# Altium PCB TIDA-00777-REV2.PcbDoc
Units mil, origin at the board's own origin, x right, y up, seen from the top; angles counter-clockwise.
Board outline 1496.06 x 4202.76 mil, 4 copper layers (Top Layer, Layer 2, Layer 3, Bottom Layer), stack 70.356 mil thick; 108 components, 64 nets, 316 pads, 62 vias.
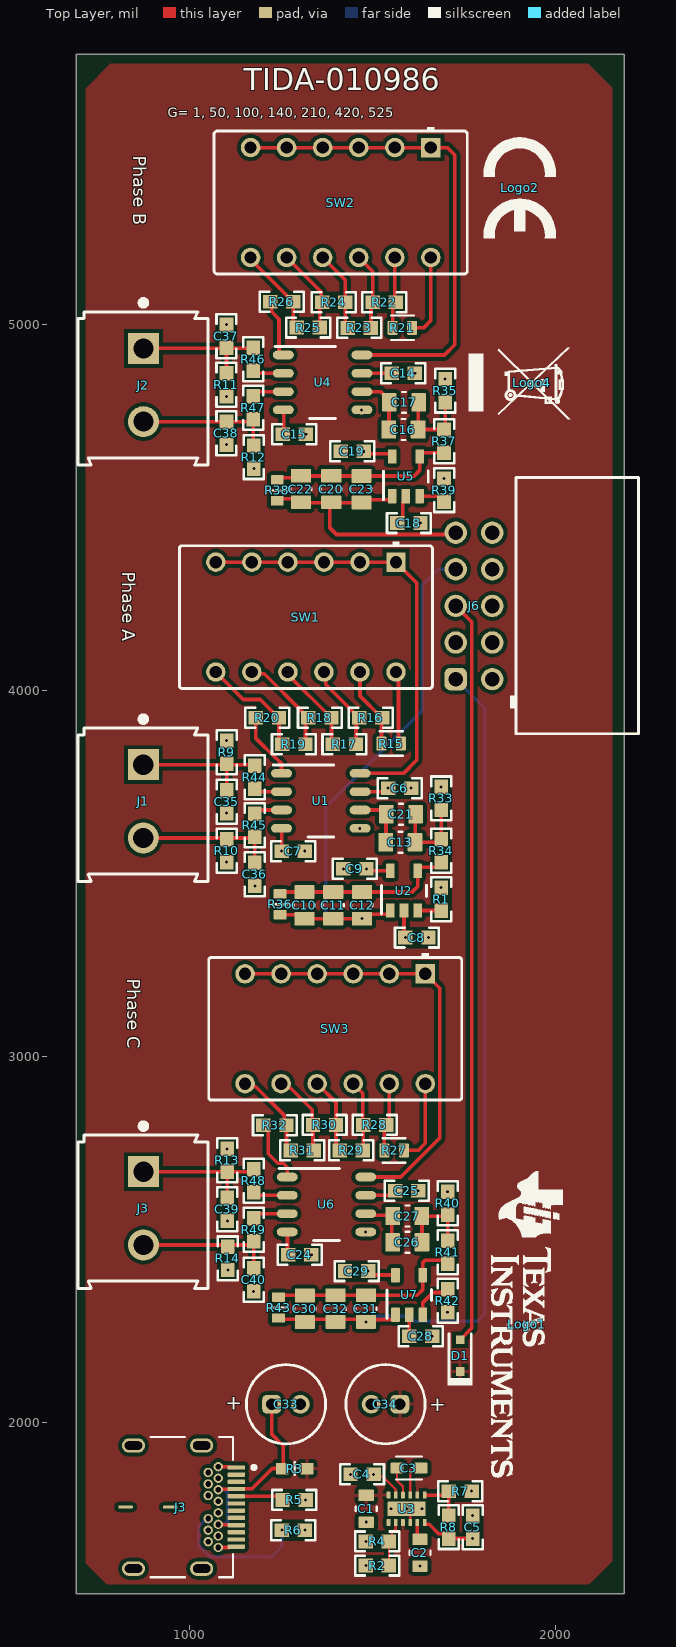
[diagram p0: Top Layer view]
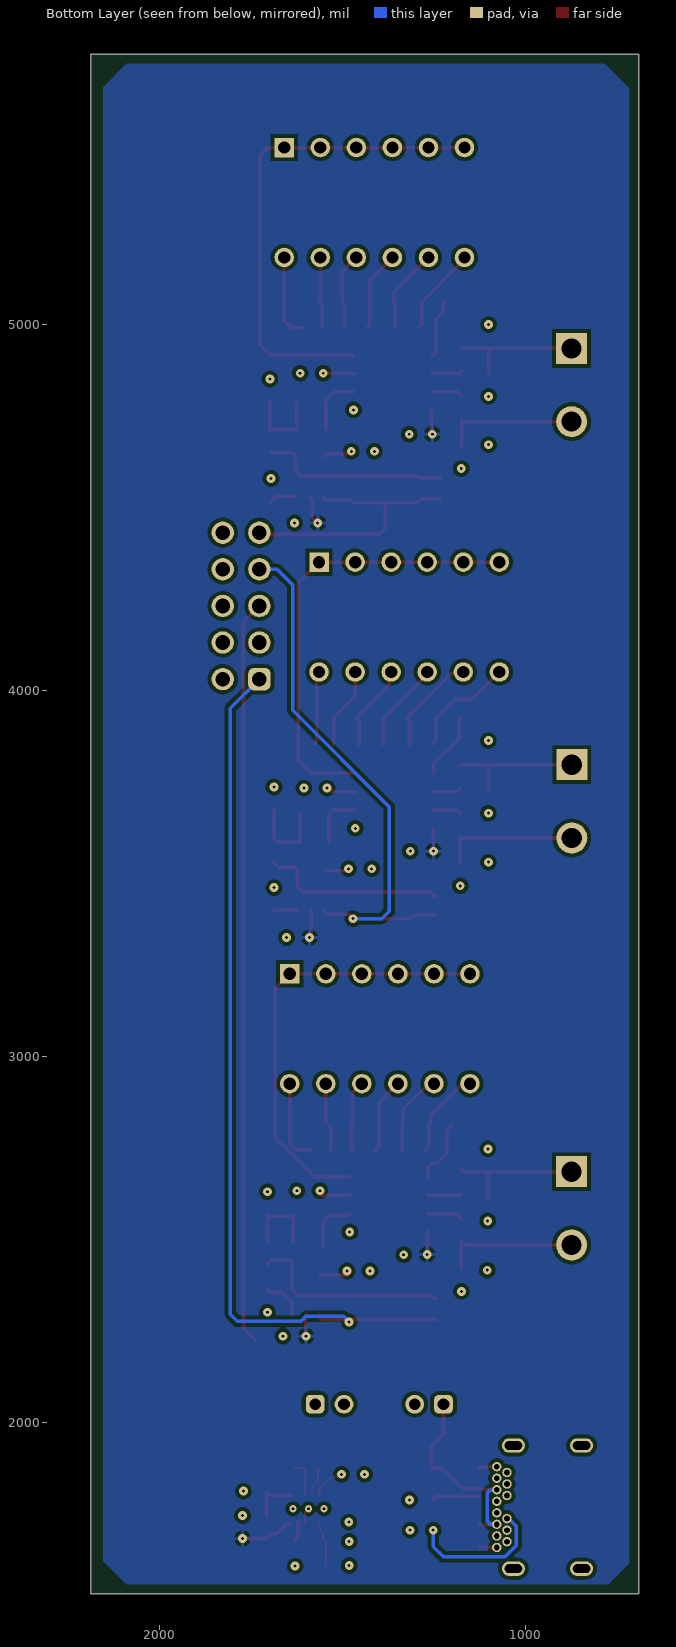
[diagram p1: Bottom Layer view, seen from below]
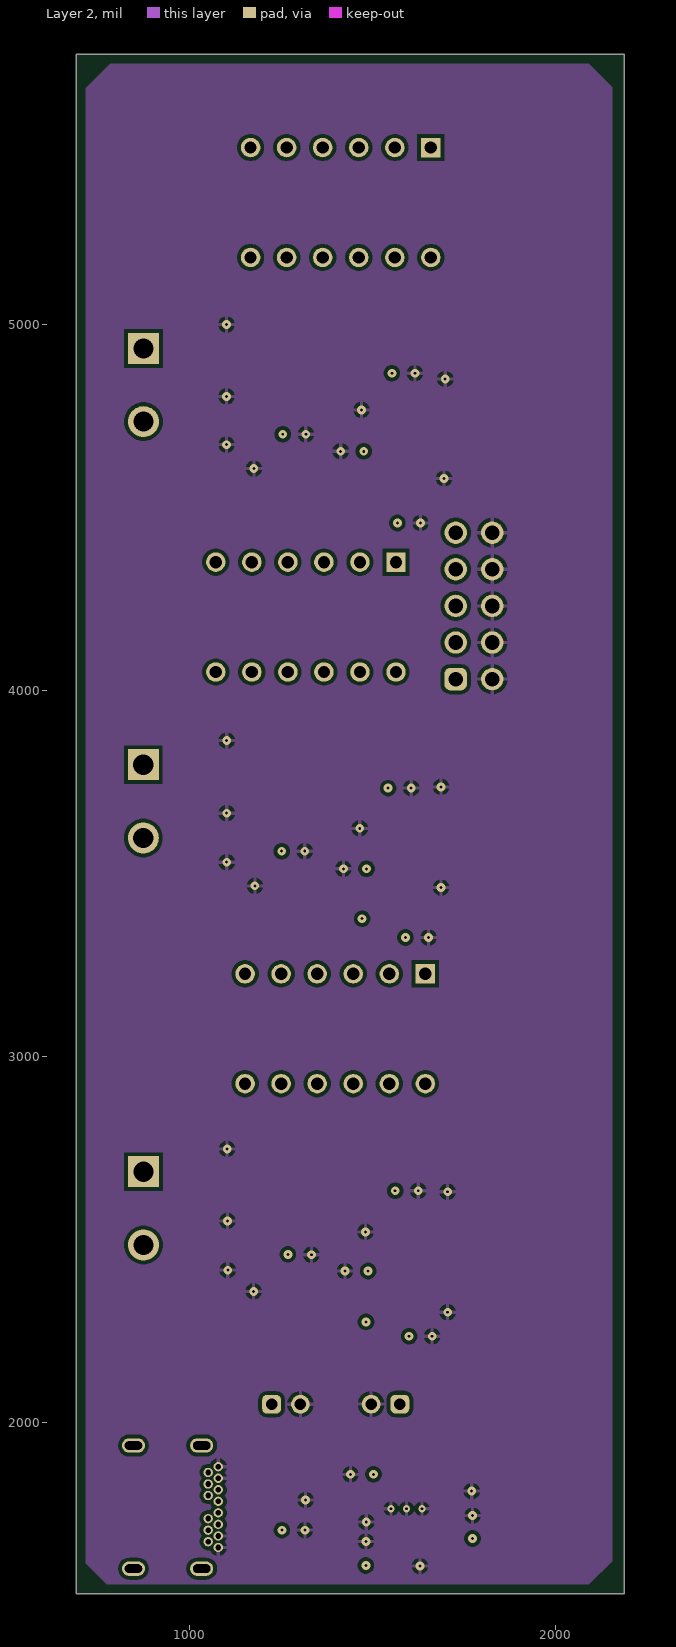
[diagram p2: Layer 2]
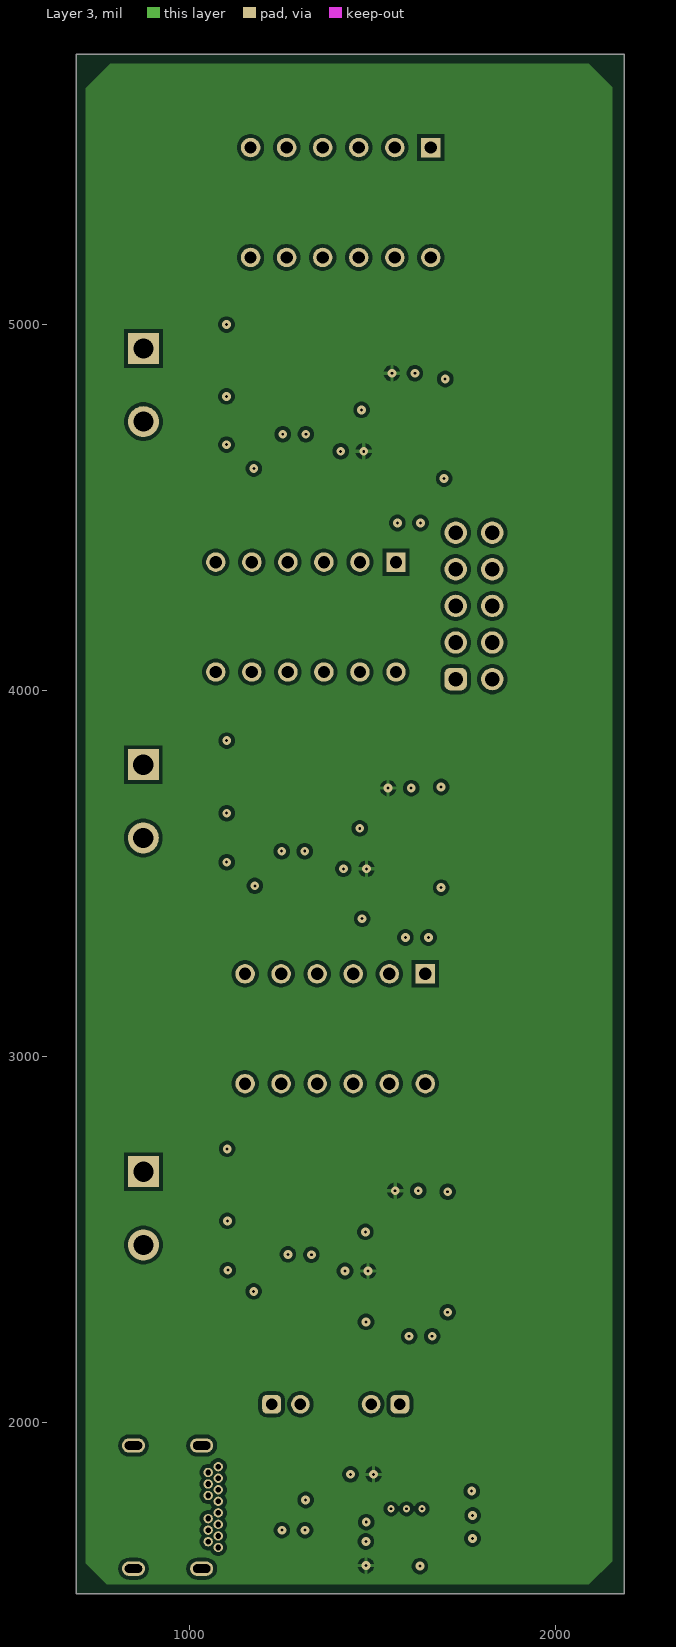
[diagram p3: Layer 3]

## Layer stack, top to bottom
Top Solder: solder mask 0.4, Solder Resist, Dk 3.5
Top Layer: signal copper 1.4
Dielectric 1: prepreg 2.8, PP-006, Dk 4.1
Layer 2: signal copper 1.378
Dielectric2: core 59.2, FR-4 High Tg, Dk 4.8
Layer 3: signal copper 1.378
Dielectric 3: prepreg 2.8, PP-006, Dk 4.1
Bottom Layer: signal copper 1.4
Bottom Solder: solder mask 0.4, Solder Resist, Dk 3.5

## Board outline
692,5736.76 2188.06,5736.76 2188.06,1534 692,1534

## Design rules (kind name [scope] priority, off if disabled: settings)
AcuteAngle [All] p1: minimum=4.50000000000000E+0001 checktracksonly=FALSE
AssemblyTestPointUsage [All] p1: valid=2
BoardOutlineClearance BoardOutlineClearance_MountingHoles [OnCopper and InComponentClass('Mounting Holes')] p1: gap=39.37 ignorepadtopadclearanceinfootprint=FALSE
BoardOutlineClearance BoardOutlineClearance_Poly [OnCopper and IsPoly] p2: gap=25 ignorepadtopadclearanceinfootprint=FALSE
BoardOutlineClearance [OnCopper and Not InComponentClass('Logo') and not InComponentClass('FiducialMark') and not InRegion(1000,500,4000,800) and not InPoly] p3: gap=40 ignorepadtopadclearanceinfootprint=FALSE
Clearance Clearance_Keepouts [((IsTrack Or IsArc) And Not InPoly) And IsFree and IsKeepOut vs ((IsTrack Or IsArc) And Not InPoly) And IsFree and IsKeepOut] p1: gap=0 ignorepadtopadclearanceinfootprint=FALSE
Clearance Clearance_Poly [InPolygon] p2: gap=10 ignorepadtopadclearanceinfootprint=TRUE
Clearance Clearance_FiducialMark [IsKeepOut and InComponentClass('FiducialMark') vs IsPad and InComponentClass('FiducialMark')] p3: gap=0 ignorepadtopadclearanceinfootprint=FALSE
Clearance [All] p4: gap=7.87 ignorepadtopadclearanceinfootprint=TRUE
ComponentClearance ComponentClearance_MountingHoles_FiducialMarks [InComponentClass('Mounting Holes') vs InComponentClass('FiducialMark')] p1: gap=50 collisioncheckmode=3 verticalgap=10 showdistances=FALSE
ComponentClearance ComponentClearance_Shunt [InComponentClass('Header') vs InComponentClass('Shunt')] p2: gap=0 collisioncheckmode=3 verticalgap=0 showdistances=FALSE
ComponentClearance ComponentClearance_Logo [InComponentClass('Logo')] p3: gap=30 collisioncheckmode=3 verticalgap=10 showdistances=FALSE
ComponentClearance ComponentClearance_ScrewToNut [(HasFootprint('NY PMS 440 0025 PH')) vs (HasFootprint('Keystone_1902C'))] p4: gap=5 collisioncheckmode=3 verticalgap=10 showdistances=FALSE
ComponentClearance ComponentClearance_MountingHoles [InComponentClass('Mounting Holes')] p5: gap=100 collisioncheckmode=3 verticalgap=100000 showdistances=FALSE
ComponentClearance ComponentClearance_SmallPassives [HasFootprint('0201*') or HasFootprint('0402*') or HasFootprint('0508') or HasFootprint('0603*') or HasFootprint('0612') or HasFootprint('0805*') or HasFootprint('0815*') or HasFootprint('0830*') or HasFootprint('1206*') or HasFootprint('1210*') or HasFootprint('1808*') or HasFootprint('1812*') or HasFootprint('1825*') or HasFootprint('2010*') or HasFootprint('2220*') or HasFootprint('2225*') or HasFootprint('2512*') or HasFootprint('2728*') or HasFootprint('3518*') vs HasFootprint('0201*') or HasFootprint('0402*') or HasFootprint('0508') or HasFootprint('0603*') or HasFootprint('0612') or HasFootprint('0805*') or HasFootprint('0815*') or HasFootprint('0830*') or HasFootprint('1206*') or HasFootprint('1210*') or HasFootprint('1808*') or HasFootprint('1812*') or HasFootprint('1825*') or HasFootprint('2010*') or HasFootprint('2220*') or HasFootprint('2225*') or HasFootprint('2512*') or HasFootprint('2728*') or HasFootprint('3518*')] p6: gap=14.96 collisioncheckmode=3 verticalgap=10 showdistances=FALSE
ComponentClearance ComponentClearance_THtoSMT [IsThruComponent vs IsSMTComponent] p7: gap=30 collisioncheckmode=3 verticalgap=30 showdistances=FALSE
ComponentClearance ComponentClearance_THtoTH [IsThruComponent vs IsThruComponent] p8: gap=20 collisioncheckmode=3 verticalgap=30 showdistances=FALSE
ComponentClearance [All] p9: gap=20 collisioncheckmode=3 verticalgap=10 showdistances=FALSE
DiffPairsRouting [All] p1: maxlimit=100 minlimit=10 mostfreqgap=10 toplayer_minwidth=15 toplayer_maxwidth=15 toplayer_prefwidth=15 midlayer1_minwidth=15 midlayer1_maxwidth=15 midlayer1_prefwidth=15 midlayer2_minwidth=15 midlayer2_maxwidth=15 midlayer2_prefwidth=15 bottomlayer_minwidth=15 bottomlayer_maxwidth=15 bottomlayer_prefwidth=15 maxuncoupledlength=1000
FabricationTestPointUsage TestPointUsage [All] p1: valid=2 allowmultiple=FALSE
FabricationTestpoint Testpoint [All] p1: side=3 testpointundercomponent=TRUE minsize=40 maxsize=100 preferedsize=60 minholesize=0 maxholesize=40 preferedholesize=32 testpointgrid=1 allowsidetop=TRUE allowsidebottom=TRUE usegrid=TRUE gridtolerance=0.01
FanoutControl Fanout_LCC [IsLCC] p1: bgadir=Out bgaviamode=Centered fanoutstyle=Auto fanoutdirection=Alternating viagrid=1 // Fanout_LCC (Default Rule)
FanoutControl Fanout_BGA [IsBGA] p2: bgadir=Out bgaviamode=Centered fanoutstyle=Auto fanoutdirection=Alternating viagrid=1 // Fanout_BGA (Default Rule)
FanoutControl Fanout_Default [All] p4: bgadir=Out bgaviamode=Centered fanoutstyle=Auto fanoutdirection=Alternating viagrid=1 // Fanout_Default (Default Rule)
FanoutControl Fanout_Small [(CompPinCount < 5)] p5: bgadir=Out bgaviamode=Centered fanoutstyle=Auto fanoutdirection=OutThenIn viagrid=1 // Fanout_Small (Default Rule)
HoleSize [All] p1: absolutevalues=TRUE maxlimit=251 minlimit=7.87 maxpercent=80.000 minpercent=20.000
MinimumAnnularRing MinimumAnnularRing_ThermalPadVias [IsVia and InAnyComponent] p1: minimumring=5.91
MinimumAnnularRing [All] p2: minimumring=7.87
MinimumSolderMaskSliver MinimumSolderMaskSliver_Logo [InComponentClass('Logo') vs InComponentClass('Logo')] p1: minsoldermaskwidth=0.7
MinimumSolderMaskSliver [All] p2: minsoldermaskwidth=3.94
PlaneConnect [All] p1: planeconnectstyle=Relief reliefexpansion=10 reliefentries=4 reliefconductorwidth=10 reliefairgap=10
PolygonConnect [All] p1: connectstyle=Relief reliefconductorwidth=10 reliefentries=4 polygonreliefangle="90 Angle" airgapwidth=10
RoutingLayers [All] p1: top layer_v5=TRUE mid layer 1_v5=FALSE mid layer 2_v5=FALSE bottom layer_v5=TRUE
RoutingVias [All] p1: holewidth=16 width=34 viastyle="Through Hole" minholewidth=7.87 minwidth=24 maxholewidth=40 maxwidth=65
SilkToBoardRegionClearance [Not ((IsComment or IsDesignator) And (Hide <> 'False')) and not InRegion(1000,500,4000,800)] p1:
SilkToSilkClearance SilkToSilkClearance_Pb-FreeLogo [(HasFootprint('Pb-Free_Overlay_Medium') OR HasFootprint('Pb-Free_Overlay_Small')) vs (HasFootprint('Pb-Free_Overlay_Medium') OR HasFootprint('Pb-Free_Overlay_Small'))] p1: silktosilkclearance=0
SilkToSilkClearance [All] p2: silktosilkclearance=3.94
SilkToSolderMaskClearance SilkToComponentPadClearance [(IsPad or IsFill or IsRegion) and InAnycomponent] p1: minsilkscreentomaskgap=5 clearancetoexposedcopper=TRUE
SilkToSolderMaskClearance "Silk to Solder Mask Opening" [All] p2: minsilkscreentomaskgap=3.94 clearancetoexposedcopper=FALSE
SolderMaskExpansion [All] p1: expansion=1.97 istentingtop=FALSE
SupplyNets "Schematic Supply Nets_21" [InNet('1_RG_P3')] p1: voltage=0.000
SupplyNets "Schematic Supply Nets_20" [InNet('INPUT_3_N')] p2: voltage=0.000
SupplyNets "Schematic Supply Nets_19" [InNet('INPUT_2_P')] p3: voltage=0.000
SupplyNets "Schematic Supply Nets_18" [InNet('2_RG_P1')] p4: voltage=0.000
SupplyNets "Schematic Supply Nets_17" [InNet('Phase C')] p5: voltage=0.000
SupplyNets "Schematic Supply Nets_16" [InNet('2_RG_P3')] p6: voltage=0.000
SupplyNets "Schematic Supply Nets_15" [InNet('1_RG_P2')] p7: voltage=0.000
SupplyNets "Schematic Supply Nets_14" [InNet('INPUT_3_P')] p8: voltage=0.000
SupplyNets "Schematic Supply Nets_13" [InNet('1_RG_P1')] p9: voltage=0.000
SupplyNets "Schematic Supply Nets_12" [InNet('-2V5')] p10: voltage=0.000
SupplyNets "Schematic Supply Nets_11" [InNet('Phase B')] p11: voltage=0.000
SupplyNets "Schematic Supply Nets_10" [InNet('2_RG_P2')] p12: voltage=0.000
SupplyNets "Schematic Supply Nets_9" [InNet('Phase A')] p13: voltage=0.000
SupplyNets "Schematic Supply Nets_8" [InNet('SW_Phase_A')] p14: voltage=0.000
SupplyNets "Schematic Supply Nets_7" [InNet('VCC')] p15: voltage=0.000
SupplyNets "Schematic Supply Nets_6" [InNet('INPUT_1_N')] p16: voltage=0.000
SupplyNets "Schematic Supply Nets_5" [InNet('SW_Phase_B')] p17: voltage=0.000
SupplyNets "Schematic Supply Nets_4" [InNet('SW_Phase_C')] p18: voltage=0.000
SupplyNets "Schematic Supply Nets_3" [InNet('+2V5')] p19: voltage=0.000
SupplyNets "Schematic Supply Nets_2" [InNet('INPUT_2_N')] p20: voltage=0.000
SupplyNets "Schematic Supply Nets_1" [InNet('INPUT_1_P')] p21: voltage=0.000
SupplyNets "Schematic Supply Nets" [InNet('GND')] p22: voltage=0.000
UnRoutedNet [All] p1: checkbadconnections=TRUE
Width [All] p1: maxlimit=100 minlimit=6 preferedwidth=10 checkconnectedcopper=TRUE
13 further rules are at their usual default settings.

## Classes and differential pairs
component class TIDA-00777-REV2_Power: C1 C2 C3 C4 C5 C33 C34 J3 R2 R3 R4 R5 R6 R7 R8 U3
component class TIDA-00777-REV2_AFE: C6 C7 C8 C9 C10 C11 C12 C13 C14 C15 C16 C17 C18 C19 C20 C21 C22 C23 C24 C25 C26 C27 C28 C29 C30 C31 C32 C35 C36 C37 C38 C39 C40 D1 J1 J2 J3 J6 R1 R9 R10 R11 R12 R13 R14 R15 R16 R17 R18 R19 R20 R21 R22 R23 R24 R25 R26 R27 R28 R29 R30 R31 R32 R33 R34 R35 R36 R37 R38 R39 R40 R41 R42 R43 R44 R45 R46 R47 R48 R49 SW1 SW2 SW3 U1 U2 U4 U5 U6 U7
component class Logo: Logo1
component class TIDA-00777-REV2_Hardware: Logo1 Logo2 Logo4

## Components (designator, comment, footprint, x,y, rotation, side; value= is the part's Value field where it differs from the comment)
C1 "CGA4J1X7R1H475K125AC" FP-CGA4J1X7R1H475K125AC_0805-MFG 1483.44,1765.53 r90 top value=4.7µF
C2 "CGA4J1X7R1H475K125AC" FP-CGA4J1X7R1H475K125AC_0805-MFG 1630,1645.45 r270 top value=4.7µF
C3 "GMC10X7R105K50NT" FP-GMC10X7R105K50NT_0603-MFG 1600.09,1876.76 r180 top value=1µF
C4 "C1608X5R1V225K080AC" 0603 1471.85,1859.62 r180 top value=2.2uF
C5 "C1608X5R1V225K080AC" 0603 1773.85,1715.58 r270 top value=2.2uF
C6 "06035C104JAT2A" 0603 1574.66,3733.32 r180 top value=0.1uF
C7 "06035C104JAT2A" 0603 1283.99,3561.1 r0 top value=0.1uF
C8 "06035C104JAT2A" 0603 1621.9,3325.34 r180 top value=0.1uF
C9 "06035C104JAT2A" 0603 1452.5,3513.01 r0 top value=0.1uF
C10 "AC0805KRX7R8BB104" FP-AC0805KRX7R8BB104_0805-MFG 1314.64,3413.18 r270 top value=100nF
C11 "AC0805KRX7R8BB104" FP-AC0805KRX7R8BB104_0805-MFG 1393.38,3413.18 r270 top value=100nF
C12 "AC0805KRX7R8BB104" FP-AC0805KRX7R8BB104_0805-MFG 1472.12,3413.18 r270 top value=100nF
C13 "GMC21X5R226M35NT" FP-GMC21X5R226M35NT_0805-MFG 1576.63,3585.54 r180 top value=22µF
C14 "06035C104JAT2A" 0603 1584.83,4866.09 r180 top value=0.1uF
C15 "06035C104JAT2A" 0603 1286.94,4699.68 r0 top value=0.1uF
C16 "GMC21X5R226M35NT" FP-GMC21X5R226M35NT_0805-MFG 1584.83,4712.52 r180 top value=22µF
C17 "GMC21X5R226M35NT" FP-GMC21X5R226M35NT_0805-MFG 1586.64,4786.65 r0 top value=22µF
C18 "06035C104JAT2A" 0603 1599.99,4457.23 r180 top value=0.1uF
C19 "06035C104JAT2A" 0603 1445.11,4652.99 r0 top value=0.1uF
C20 "AC0805KRX7R8BB104" FP-AC0805KRX7R8BB104_0805-MFG 1388,4550 r270 top value=100nF
C21 "GMC21X5R226M35NT" FP-GMC21X5R226M35NT_0805-MFG 1578.44,3662.08 r0 top value=22µF
C22 "AC0805KRX7R8BB104" FP-AC0805KRX7R8BB104_0805-MFG 1305,4550 r270 top value=100nF
C23 "AC0805KRX7R8BB104" FP-AC0805KRX7R8BB104_0805-MFG 1470.61,4549.39 r270 top value=100nF
C24 "06035C104JAT2A" 0603 1302.13,2459.2 r0 top value=0.1uF
C25 "06035C104JAT2A" 0603 1593.88,2633.93 r180 top value=0.1uF
C26 "GMC21X5R226M35NT" FP-GMC21X5R226M35NT_0805-MFG 1595.69,2493.25 r0 top value=22µF
C27 "GMC21X5R226M35NT" FP-GMC21X5R226M35NT_0805-MFG 1595.4,2564.79 r180 top value=22µF
C28 "06035C104JAT2A" 0603 1631.87,2236.62 r180 top value=0.1uF
C29 "06035C104JAT2A" 0603 1456.98,2414.74 r0 top value=0.1uF
C30 "AC0805KRX7R8BB104" FP-AC0805KRX7R8BB104_0805-MFG 1315.91,2311.77 r270 top value=100nF
C31 "AC0805KRX7R8BB104" FP-AC0805KRX7R8BB104_0805-MFG 1482.72,2312.16 r270 top value=100nF
C32 "AC0805KRX7R8BB104" FP-AC0805KRX7R8BB104_0805-MFG 1399.73,2312.16 r270 top value=100nF
C33 "860020572003" WCAP-ATG5_D5H11 1264.32,2050.95 r180 top
C34 "860020572003" WCAP-ATG5_D5H11 1535.95,2051.26 r0 top
C35 "C0603H103J3GACTU" 0603 1102.39,3696.38 r270 top value=0.01uF
C36 "C0603H103J3GACTU" 0603 1179.18,3498.01 r90 top value=0.01uF
C37 "C0603H103J3GACTU" 0603 1101.76,4967.61 r90 top value=0.01uF
C38 "C0603H103J3GACTU" 0603 1101.76,4702.68 r90 top value=0.01uF
C39 "C0603H103J3GACTU" 0603 1104.21,2583.04 r270 top value=0.01uF
C40 "C0603H103J3GACTU" 0603 1175.96,2390.67 r90 top value=0.01uF
D1 "SD103AWS-7-F" SOD-323 1739.85,2183.67 r90 top value=40V
J1 "282841-2" TEC_282841-2 874.62,3697.31 r270 top
J2 "282841-2" TEC_282841-2 875,4834 r270 top
J3 "282841-2" TEC_282841-2 875,2586 r270 top
J3 "632723300011" FP-632723300011_CONN_USB_8MM74_11MM20-MFG 895.09,1770.22 r270 top
J6 "SFH11-PBPC-D05-RA-BK" Sullins_SFH11-PBPC-D05-RA-BK 2060.11,4230.85 r90 top
Logo1 "Texas Instruments" TI_Stacked_Overlay_Small 1922.32,2268.97 r270 top
Logo2 "CE Mark" CE_Mark_5mm 1902.63,5372.58 r270 top
Logo4 "WEEE logo" WEEE_Minimum 1935.47,4840.63 r270 top
R1 "RT0603BRD079K88L" 0603 1687.86,3430.16 r270 top value=9.88k
R2 "RT0603BRD0754K2L" 0603 1513.89,1610.58 r0 top value=54.2k
R3 "RC0603JR-130RP" FP-RC0603JR-130RP_0603-MFG 1288.2,1875.46 r0 top value=0
R4 "RT0603DRE0750K5L" 0603 1513.89,1676.3 r0 top value=50.5k
R5 "RG1608P-512-B-T5" 0603 1286.33,1789.62 r0 top value=5.10k
R6 "RG1608P-512-B-T5" 0603 1284.52,1707.23 r0 top value=5.10k
R7 "RT0603DRE0750K5L" 0603 1739.85,1813.76 r0 top value=50.5k
R8 "RT0603BRD0752K3L" 0603 1708.35,1715.78 r270 top value=52.3k
R9 "RT0603BRD0747K5L" 0603 1102.39,3831.58 r270 top value=47.5k
R10 "RT0603BRD0747K5L" 0603 1102.39,3562.64 r270 top value=47.5k
R11 "RT0603BRD0747K5L" 0603 1101.76,4834.38 r90 top value=47.5k
R12 "RT0603BRD0747K5L" 0603 1176.51,4637.34 r270 top value=47.5k
R13 "RT0603BRD0747K5L" 0603 1103.62,2716.83 r270 top value=47.5k
R14 "RT0603BRD0747K5L" 0603 1105.01,2449.07 r270 top value=47.5k
R15 "MCT06030D5000BP100" FP-MCT06030D5000BP100_0603-MFG 1551.42,3855.14 r0 top value=500
R16 "RT0603BRD07120RL" 0603 1495.56,3925.19 r0 top value=120
R17 "RT0603BRD07120RL" 0603 1423.94,3853.36 r0 top value=120
R18 "RT0603BRD07120RL" 0603 1357.08,3925.19 r0 top value=120
R19 "RT0603BRD0723R7L" 0603 1286.09,3853.2 r0 top value=23.7
R20 "95.3" 0603 1213.59,3925.31 r180 top
R21 "MCT06030D5000BP100" FP-MCT06030D5000BP100_0603-MFG 1582.12,4989.98 r0 top value=500
R22 "RT0603BRD07120RL" 0603 1532.43,5060.13 r0 top value=120
R23 "RT0603BRD07120RL" 0603 1464.77,4989.98 r0 top value=120
R24 "RT0603BRD07120RL" 0603 1394.58,5060.13 r0 top value=120
R25 "RT0603BRD0723R7L" 0603 1325.01,4990.91 r0 top value=23.7
R26 "95.3" 0603 1252.77,5061.71 r180 top
R27 "MCT06030D5000BP100" FP-MCT06030D5000BP100_0603-MFG 1559.54,2744.03 r0 top value=500
R28 "RT0603BRD07120RL" 0603 1506.53,2813.53 r0 top value=120
R29 "RT0603BRD07120RL" 0603 1442.19,2744.03 r0 top value=120
R30 "RT0603BRD07120RL" 0603 1369.42,2813.53 r0 top value=120
R31 "RT0603BRD0723R7L" 0603 1308.21,2744.03 r0 top value=23.7
R32 "95.3" 0603 1234.12,2813.13 r180 top
R33 "RT0603BRD0750K5L" 0603 1687.86,3705.06 r90 top value=50.5k
R34 "RT0603BRD078K87L" 0603 1687.86,3561.96 r270 top value=8.87k
R35 "RT0603BRD0750K5L" 0603 1698.91,4818.97 r90 top value=50.5k
R36 "ERA-3AEB104V" FP-ERA-3AEB104V_0603-MFG 1248.08,3416.13 r90 top value=100k
R37 "RT0603BRD078K87L" 0603 1695.93,4680.98 r270 top value=8.87k
R38 "ERA-3AEB104V" FP-ERA-3AEB104V_0603-MFG 1240.41,4546.44 r90 top value=100k
R39 "RT0603BRD079K88L" 0603 1695.93,4547.21 r270 top value=9.88k
R40 "RT0603BRD0750K5L" 0603 1705.69,2599.76 r90 top value=50.5k
R41 "RT0603BRD078K87L" 0603 1705.69,2465.57 r270 top value=8.87k
R42 "RT0603BRD079K88L" 0603 1705.69,2333.68 r90 top value=9.88k
R43 "ERA-3AEB104V" FP-ERA-3AEB104V_0603-MFG 1244.06,2314.98 r90 top value=100k
R44 "RT0603BRD0716KL" 0603 1179.18,3763.05 r270 top value=16.0k
R45 "RT0603BRD0716KL" 0603 1179.18,3632.03 r90 top value=16.0k
R46 "RT0603BRD0716KL" 0603 1174.73,4904.07 r270 top value=16.0k
R47 "RT0603BRD0716KL" 0603 1174.73,4771.83 r90 top value=16.0k
R48 "RT0603BRD0716KL" 0603 1175.96,2661.55 r270 top value=16.0k
R49 "RT0603BRD0716KL" 0603 1176,2527 r90 top value=16.0k
SW1 "76SB06ST" SW_76SB06 1318.56,4200.37 r270 top
SW2 "76SB06ST" SW_76SB06 1413.69,5332.33 r270 top
SW3 "76SB06ST" SW_76SB06 1398.69,3076.27 r270 top
U1 "INA828ID" D0008A_N 1359.36,3698.52 r0 top
U2 "TLV9001RIDBVR" DBV0005A_N 1586.43,3453.29 r90 top
U3 "LM27762DSSR" DSS0012B 1593.47,1765.53 r90 top
U4 "INA828ID" D0008A_N 1364.31,4841.09 r0 top
U5 "TLV9001RIDBVR" DBV0005A_N 1591.72,4584.74 r90 top
U6 "INA828ID" D0008A_N 1374.78,2596.48 r0 top
U7 "TLV9001RIDBVR" DBV0005A_N 1600.66,2349.59 r90 top

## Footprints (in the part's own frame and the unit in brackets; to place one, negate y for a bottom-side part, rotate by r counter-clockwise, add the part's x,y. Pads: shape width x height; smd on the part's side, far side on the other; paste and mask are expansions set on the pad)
0603 [mm] "0603 from SM-752 data"
  rect 1x0.95 smd: 1(-0.8,0) 2(0.8,0)
  silkscreen extent -1.52,-0.69 1.52,0.69, body extent -0.87,-0.47 0.87,0.47, height 1
CE_Mark_5mm [mil] "Minimum text height for CE Mark"
  silkscreen extent -138,-98 138,98
D0008A_N [mm] "SOIC, 8-Leads, Body 4.9x3.9mm, Pitch 1.27mm, IPC Medium Density"
  oval 1.45x0.6 smd: 1(-2.725,1.905) 2(-2.725,0.635) 3(-2.725,-0.635) 4(-2.725,-1.905) 5(2.725,-1.905) 6(2.725,-0.635) 7(2.725,0.635) 8(2.725,1.905)
  silkscreen extent -3.3,-2.5 0.9,2.5, body extent -3,-2.45 3,2.45, height 1.63
DBV0005A_N [mm] "SOT23, 5-Leads, Body 2.9x1.6mm, Pitch 0.95mm, Lead Span 2.8mm, IPC Medium Density"
  rrect17% 1x0.6 smd: 1(-1.375,0.95) 2(-1.375,0) 3(-1.375,-0.95) 4(1.375,-0.95) 5(1.375,0.95)
  silkscreen extent -1.63,-1.55 0.38,1.55, body extent -1.42,-1.46 1.42,1.46, height 1.09
DSS0012B [mm] "WSON-10"
  rrect40% 0.5x0.25 smd: 1(-0.95,1.25) 2(-0.95,0.75) 3(-0.95,0.25) 4(-0.95,-0.25) 5(-0.95,-0.75) 6(-0.95,-1.25) 7(0.95,-1.25) 8(0.95,-0.75) 9(0.95,-0.25) 10(0.95,0.25) 11(0.95,0.75) 12(0.95,1.25)
  rrect11% 1x2.65 smd paste-0.5: 13(0,0)
  body extent -1,-1.5 1,1.5, height 0.81
FP-632723300011_CONN_USB_8MM74_11MM20-MFG [mm]
  round 0.65 hole 0.4 paste-2539.97 mask+0: 1(-2,4.68) 2(2,4.68) B1(2.8,4.68) B2(2.4,3.98) B3(1.6,3.98) B4(1.2,4.68) B5(0.8,3.98) B6(0.4,4.68) B7(-0.4,4.68) B8(-0.8,3.98) B9(-1.2,4.68) B10(-1.6,3.98) B11(-2.4,3.98) B12(-2.8,4.68)
  rrect100% 1x1.6 hole 1.2 slot 0.6 at 0 deg paste-2539.97 mask+0: 3(-4.27,3.53) 4(4.27,3.53) 6(-4.27,-1.2) 7(4.27,-1.2)
  rrect50% 0.2x1 smd paste+0 mask+0: 5(0,1.35) 8(0,-1.75)
  rrect33% 0.3x1.2 smd paste+0 mask+0: A1(-2.75,5.93) A2(-2.25,5.93) A3(-1.75,5.93) A4(-1.25,5.93) A5(-0.75,5.93) A6(-0.25,5.93) A7(0.25,5.93) A8(0.75,5.93) A9(1.25,5.93) A10(1.75,5.93) A11(2.25,5.93) A12(2.75,5.93)
  silkscreen extent -4.87,-0.03 4.87,7.28, body extent -4.87,-5.77 4.87,6.63, height 0.25
FP-AC0805KRX7R8BB104_0805-MFG [mm]
  rrect11% 0.95x1.4 smd paste+0 mask+0: 1(-0.925,0) 2(0.925,0)
  silkscreen extent -0.08,-0.72 0.08,0.72, body extent -1.6,-1.05 1.6,1.05, height 0.25
FP-CGA4J1X7R1H475K125AC_0805-MFG [mm]
  rrect13% 0.8x1.05 smd paste+0 mask+0: 1(-0.925,0) 2(0.925,0)
  silkscreen extent -0.15,-0.72 0.15,0.72, body extent -1.43,-0.82 1.43,0.82, height 0.25
FP-ERA-3AEB104V_0603-MFG [mm]
  rrect15% 0.65x0.9 smd paste+0 mask+0: 1(-0.725,0) 2(0.725,0)
  silkscreen extent 0,-0.5 0,0.5, body extent -1.15,-0.6 1.15,0.6, height 0.25
FP-GMC10X7R105K50NT_0603-MFG [mil]
  rrect13% 35x30 smd paste+0 mask+0: 1(-32.5,0) 2(32.5,0)
  silkscreen extent -35,-31 35,31, body extent -54,-24 54,24, height 10
FP-GMC21X5R226M35NT_0805-MFG [mil]
  rrect10% 40x50 smd paste+0 mask+0: 1(-40,0) 2(40,0)
  silkscreen extent -5,-29 5,29, body extent -64,-32 64,32, height 10
FP-MCT06030D5000BP100_0603-MFG [mm]
  rrect14% 0.7x0.95 smd paste+0 mask+0: 1(-0.675,0) 2(0.675,0)
  silkscreen extent -0.8,-0.85 0.8,0.85, body extent -1.12,-0.58 1.12,0.58, height 0.25
FP-RC0603JR-130RP_0603-MFG [mm]
  rrect13% 0.9x0.8 smd paste+0 mask+0: 1(-0.85,0) 2(0.85,0)
  silkscreen extent 0,-0.45 0,0.45, body extent -1.4,-0.55 1.4,0.55, height 0.25
SOD-323 [mm] "NXP recommended land pattern"
  rect 0.6x0.6 smd paste-0.05: 1(-1.1,0) 2(1.1,0)
  silkscreen extent -2.06,-0.86 1.53,0.86, body extent -1.3,-0.67 1.3,0.68, height 1.1
Sullins_SFH11-PBPC-D05-RA-BK [mm] "Receptacle, 2.54mm, 5x2, R/A, TH"
  rrect50% 1.55x1.55 hole 1.02: 1(-5.08,8.445)
  round 1.55 hole 1.02: 2(-5.08,5.905) 3(-2.54,8.445) 4(-2.54,5.905) 5(0,8.445) 6(0,5.905) 7(2.54,8.445) 8(2.54,5.905) 9(5.08,8.445) 10(5.08,5.905)
  silkscreen extent -8.86,-4.25 8.92,4.67, body extent -8.9,-4.23 8.88,8.61, height 7
SW_76SB06 [mm] "TH, 12-Leads, Body 9.65x17.3mm, Pitch 2.5mm"
  rect 1.35x1.35 hole 0.85: 1(-3.81,6.25)
  round 1.35 hole 0.85: 2(-3.81,3.75) 3(-3.81,1.25) 4(-3.81,-1.25) 5(-3.81,-3.75) 6(-3.81,-6.25) 7(3.81,-6.25) 8(3.81,-3.75) 9(3.81,-1.25) 10(3.81,1.25) 11(3.81,3.75) 12(3.81,6.25)
  silkscreen extent -5.25,-8.78 4.95,8.78, body extent -4.95,-8.78 4.95,8.78, height 7.98
TEC_282841-2 [mm] "TE Connectivity"
  rect 2.15x2.15 hole 1.4: 1(-2.54,0)
  round 2.15 hole 1.4: 2(2.54,0)
  silkscreen extent -5.9,-4.52 5.55,4.47, body extent -5.08,-4.52 5.58,4.48, height 15.2
TI_Stacked_Overlay_Small [mil]
  silkscreen extent -418,-98 418,98
WCAP-ATG5_D5H11 [mm] "Aluminum Electrolytic Capacitors, 5x11mm"
  rrect50% 1.3x1.3 hole 0.8: 1(1,0)
  round 1.3 hole 0.8: 2(-1,0)
  silkscreen extent -2.75,-2.75 2.75,2.75, body extent -2.49,-2.5 2.5,2.5, height 11.31
WEEE_Minimum [mil] "WEEElie bin"
  silkscreen extent -95,-172 99,104

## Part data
C1 C2: library part CMP-0090082-1, "Cap Ceramic 4.7uF 50V X7R 10% Pad SMD 0805 +125°C Automotive T/R", Manufacturer="TDK Corporation", Operating Temperature Range="-55°C to +125°C", TempCo=15%, Temperature Characteristic=X7R, Tolerance_%=0.1%, ValueDisplayed=4.7uF
C3: library part CMP-0095295-1, "1 µF ±10% 50V Ceramic Capacitor X7R 0603 (1608 Metric)", Digikey Part Number=2571-GMC10X7R105K50NTTR-ND, Manufacturer="Cal-Chip Electronics", Operating Temperature Range="-55°C to +125°C", TempCo=30ppm/°C, Temperature Characteristic=X7R, Tolerance_%=10%, ValueDisplayed=1uF
C4 C5: library part CMP-0007020-5, "CAP, CERM, 2.2 uF, 35 V, +/- 10%, X5R, 0603", Cap_Case=0603, Manufacturer=TDK, Supplier Part Number 1=445-8025-1-ND, TempCo=X5R, Tolerance_%=10%, Value1="0.007674 ohm", Value2=35V, ValueDisplayed=2.2uF
C6 C7 C8 C9 C14 C15 C18 C19 C24 C25 C28 C29: library part CMP-0083854-1, "CAP, CERM, 0.1 µF, 50 V,+/- 5%, X7R, 0603", Cap_Case=0603, Manufacturer=AVX, TempCo=X7R, Tolerance_%=5%, Value2=50V, ValueDisplayed=0.1µF
C10 C11 C12 C20 C22 C23 C30 C31 C32: library part CMP-0121355-1, "0.1 µF ±10% 25V Ceramic Capacitor X7R 0805 (2012 Metric)", Digikey Part Number=311-3169-1-ND, Manufacturer=Yageo, Mouser Part Number=603-AC805KRX7R8BB104, Operating Temperature Range="-55°C to +125°C", TempCo=15%, Temperature Characteristic=X7R, Tolerance_%=10%, ValueDisplayed=100nF
C13 C16 C17 C21 C26 C27: library part CMP-0120897-1, "22 µF ±20% 35V Ceramic Capacitor X5R 0805 (2012 Metric)", Digikey Part Number=4713-GMC21X5R226M35NTCT-ND, Manufacturer="Cal-Chip Electronics", Operating Temperature Range="-55°C to +85°C", TempCo=15%, Temperature Characteristic=X5R, Tolerance_%=20%, ValueDisplayed=22uF
C33 C34: library part CMP-0109532-1, "WCAP-ATG5 Aluminum Electrolytic Capacitor, Radial, THT, D5 x H11mm, 10µF, 35V", Capacitance Tolerance=+/-20%, Leakage Current=3.5uA, Manufacturer="Wurth Elektronik", Operating Temperature Max=105°C, Operating Temperature Min=-40°C, Rated Voltage (DC)=35V, Ripple Current=46mA
C35 C36 C37 C38 C39 C40: library part CMP-0006975-4, "CAP, CERM, 0.01 uF, 25 V, +/- 5%, C0G/NP0, 0603", Cap_Case=0603, Manufacturer=Kemet, Supplier Part Number 1=399-5779-1-ND, TempCo=C0G/NP0, Tolerance_%=5%, Value1=Unknown, Value2=25V, ValueDisplayed=0.01uF
D1: library part CMP-0028544-2, "Diode, Schottky, 40 V, 0.35 A, SOD-323", Manufacturer="Diodes Inc.", Value1=0.35A, Value2=0.55V
J1 J2 J3: library part CMP-0054973-1, "Terminal Block, 2x1, 5.08mm, TH", Manufacturer="TE Connectivity", Supplier Part Number 1=A98342-ND
J3: library part CMP-0091586-1, "USB-C (USB TYPE-C) USB 3.2 Gen 2 (USB 3.1 Gen 2, Superspeed + (USB 3.1)) Receptacle Connector 24 Position Surface Mount, Right Angle; Through Hole", Current_A=5A, Digikey Part Number=732-9618-1-ND, Manufacturer=Wurth, Mouser Part Number=710-632723300011, Operating Temperature Range="-40°C to +105°C", Voltage_V=20V
J6: library part CMP-0054694-1, "Receptacle, 2.54mm, 5x2, Gold, R/A, TH", Color=Black, Current_A=3A, Manufacturer="Sullins Connector Solutions", Supplier Part Number 1=S9202-ND, Voltage_V=1kV
Logo1: library part CMP-0074838-1, "Texas Instrument Corporate Signature"
Logo2: library part CMP-0074844-2, Manufacturer="Texas Instruments"
Logo4: library part CMP-0074769-4, Manufacturer="Texas Instruments"
R1 R39 R42: library part CMP-0024558-2, "RES, 9.88 k, 0.1%, 0.1 W, 0603", Manufacturer="Yageo America", Power_W=100mW, TempCo="25 ppm/C", Tolerance_%=0.1%, Value2=0.1W, Value_Code=9k88, ValueDisplayed=9.88k
R2: library part CMP-0024333-2, "RES, 54.2 k, 0.1%, 0.1 W, 0603", Manufacturer="Yageo America", Power_W=100mW, TempCo="25 ppm/C", Tolerance_%=0.1%, Value2=0.1W, Value_Code=54k2, ValueDisplayed=54.2k
R3: library part CMP-0120804-1, "Resistor Thick Film 0603 Jumper 0 Ohm ±5% 1/10W Molded Paper T/R", Digikey Part Number=13-RC0603JR-130RPCT-ND, Manufacturer=Yageo, Operating Temperature Range="-55°C to +155°C", Power_W=100mW
R4 R7: library part CMP-0025375-2, "RES, 50.5 k, 0.5%, 0.1 W, 0603", Manufacturer="Yageo America", Power_W=100mW, TempCo="50 ppm/C", Tolerance_%=0.5%, Value2=0.1W, Value_Code=50k5, ValueDisplayed=50.5k
R5 R6: library part CMP-0023568-3, "RES, 5.10 k, 0.1%, 0.1 W, 0603", Manufacturer="Susumu Co Ltd", Power_W=100mW, Supplier Part Number 1=RG16P5.1KBCT-ND, TempCo="25 ppm/C", Tolerance_%=0.1%, Value2=0.1W, Value_Code=5k10, ValueDisplayed=5.10k
R8: library part CMP-0024319-3, "RES, 52.3 k, 0.1%, 0.1 W, 0603", Manufacturer="Yageo America", Power_W=100mW, TempCo="25 ppm/C", Tolerance_%=0.1%, Value2=0.1W, Value_Code=52k3, ValueDisplayed=52.3k
R9 R10 R11 R12 R13 R14: library part CMP-0024266-3, "RES, 47.5 k, 0.1%, 0.1 W, 0603", Manufacturer="Yageo America", Power_W=100mW, TempCo="25 ppm/C", Tolerance_%=0.1%, Value2=0.1W, Value_Code=47k5, ValueDisplayed=47.5k
R15 R21 R27: library part CMP-0121720-1, "Res Thin Film 0603 500Ω 0.1% 0.1W ±25ppm/°C Molded SMD Paper  T/R", Digikey Part Number=MCT0603-100-CFCT-ND, Manufacturer=Vishay, Mouser Part Number=594-MCT06030C1000FP5, Operating Temperature Range="-55°C to +125°C", Power_W=100mW, TempCo=25ppm/°C, Tolerance_%=0.1%
R16 R17 R18 R22 R23 R24 R28 R29 R30: library part CMP-0023691-3, "RES, 120, 0.1%, 0.1 W, 0603", Manufacturer="Yageo America", Power_W=100mW, TempCo="25 ppm/C", Tolerance_%=0.1%, Value2=0.1W, Value_Code=120R, ValueDisplayed=120
R19 R25 R31: library part CMP-0023979-3, "RES, 23.7, 0.1%, 0.1 W, 0603", Manufacturer="Yageo America", Power_W=100mW, TempCo="25 ppm/C", Tolerance_%=0.1%, Value2=0.1W, Value_Code=23R7, ValueDisplayed=23.7
R20 R26 R32: library part CMP-0024541-2, "RES, 95.3, 0.1%, 0.1 W, 0603", Manufacturer="Yageo America", PartNumber=RT0603BRD0795R3L, Power_W=100mW, TempCo="25 ppm/C", Tolerance_%=0.1%, Value2=0.1W, Value_Code=95R3
R33 R35 R40: library part CMP-0024307-2, "RES, 50.5 k, 0.1%, 0.1 W, 0603", Manufacturer="Yageo America", Power_W=100mW, TempCo="25 ppm/C", Tolerance_%=0.1%, Value2=0.1W, Value_Code=50k5, ValueDisplayed=50.5k
R34 R37 R41: library part CMP-0024525-2, "RES, 8.87 k, 0.1%, 0.1 W, 0603", Manufacturer="Yageo America", Power_W=100mW, TempCo="25 ppm/C", Tolerance_%=0.1%, Value2=0.1W, Value_Code=8k87, ValueDisplayed=8.87k
R36 R38 R43: library part CMP-0046061-1, "Res Thin Film 0603 100K Ohm 0.1% 0.1W ±25ppm/°C Molded SMD Punched Carrier T/R", Digikey Part Number=P100KDBCT-ND, Manufacturer=Panasonic, Mouser Part Number=667-ERA-3AEB104V, Operating Temperature Range="-55°C to +155°C", Power=100mW, TempCo=25ppm/°C, Tolerance_%=0.1%
R44 R45 R46 R47 R48 R49: library part CMP-0023803-3, "RES, 16.0 k, 0.1%, 0.1 W, 0603", Manufacturer="Yageo America", Power_W=100mW, TempCo="25 ppm/C", Tolerance_%=0.1%, Value2=0.1W, Value_Code=16k0, ValueDisplayed=16.0k
SW1 SW2 SW3: library part CMP-0002309-1, "Switch, SPST, Off-On, 6 Pos, 0.15 A, 30 VDC, TH", CurrentRating_mA=150A, Manufacturer=Grayhill, Supplier Part Number 1=GH7173-ND
U1 U4 U6: library part CMP-0079943-1, "50-uV Offset, 7-nV/√Hz Noise, Low-Power, Precision Instrumentation Amplifier, D0008A (SOIC-8)", Alternate Manufacturer="Texas Instruments", Alternate PartNumber=INA828IDR
U2 U5 U7: library part CMP-0081555-1, "Low-Power, Rail-to-Rail In and Out, 1-MHz Operational Amplifier, DBV0005A (SOT-23-5)", Alternate Manufacturer="Texas Instruments", Alternate PartNumber=TLV9001RIDBVT
U3: library part CMP-0076280-3, "Low-Noise Positive- and Negative-Output Charge Pump With Integrated LDO, DSS0012B (WSON-12)", Alternate Manufacturer="Texas Instruments", Alternate PartNumber=LM27762DSST, Operating Temperature Range="-40 to 85 C", Rating=Catalog

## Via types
v1: diameter 24, hole 8, Top Layer to Bottom Layer, tented both sides, 59 vias
v2: diameter 19.68, hole 7.87, Top Layer to Bottom Layer, 3 vias

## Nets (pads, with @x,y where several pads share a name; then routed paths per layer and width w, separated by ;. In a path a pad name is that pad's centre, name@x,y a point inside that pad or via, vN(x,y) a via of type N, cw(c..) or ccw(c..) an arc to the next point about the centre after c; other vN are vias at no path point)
1_RG_P1: R20.2 U1.1 | length 181.5
  Top Layer w10: R20.2 1182.09,3869.11 1236.46,3814.75 1237.66,3814.75 1252.08,3800.33 U1.1
1_RG_P2: R26.2 U4.1 | length 163.6
  Top Layer w10: R26.2 1225.26,5057.72 1225.26,5033.87 1245.29,5013.83 1245.29,4922.38 1251.58,4916.09 U4.1
1_RG_P3: R32.2 U6.1 | length 177.3
  Top Layer w10: R32.2 1216.11,2799.64 1216.11,2734.72 1241.69,2709.15 1256.65,2709.15 1267.5,2698.29 U6.1
2_RG_P1: SW1.1 SW1.2 SW1.3 SW1.4 SW1.5 SW1.6 U1.8 | length 1225.9
  Top Layer w10: SW1.6 SW1.5 SW1.4 SW1.3 SW1.2 SW1.1 1621.48,4293.51 1621.48,3810.16 1584.83,3773.52 U1.8
2_RG_P2: SW2.1 SW2.2 SW2.3 SW2.4 SW2.5 SW2.6 U4.8 | length 1349.1
  Top Layer w10: SW2.6 SW2.5 SW2.4 SW2.3 SW2.2 SW2.1 1704.86,5482.33 1725.08,5462.12 1725.08,4943.83 1697.33,4916.09 U4.8
2_RG_P3: SW3.1 SW3.2 SW3.3 SW3.4 SW3.5 SW3.6 U6.8 | length 1203.2
  Top Layer w10: SW3.6 SW3.5 SW3.4 SW3.3 SW3.2 SW3.1 1684.2,3186.83 1684.2,2777.74 1577.95,2671.48 U6.8
+2V5: C4.1 C6.2 C9.2 C14.2 C19.2 C25.2 C29.2 R2.1 U1.7 U2.5 U3.11 U4.7 U5.5 U6.7 U7.5 | length 568.3
  Top Layer w6: v1(1503.34,1859.62) 1509.24,1853.73 1528.51,1853.73 1563.95,1818.29 U3.11
  Top Layer w10: U1.7@1465.66,3723.52 1527.73,3723.52 1542.21,3738.01 C6.2@1543.2,3738.01 ; U4.7@1470.61,4866.09 v1(1553.33,4866.09) ; v1(1476.6,4652.99) 1483.41,4646.18 1547.51,4646.18 1554.32,4639.36 U5.5 ; U6.7@1481.08,2621.48 1561,2621.48 C25.2@1561.35,2621.84 ; v1(1484,3513.01) 1489.58,3507.43 U2.5 ; C29.2@1486.67,2405.56 1488.51,2403.72 U7.5
  other v1: 1482.39,1610.58 1488.48,2414.74 1562.38,2633.93 1543.16,3733.32
-2V5: C5.2 C7.1 C8.2 C15.1 C18.2 C24.1 C28.2 R8.2 U1.4 U2.2 U3.6 U4.4 U5.2 U6.4 U7.2 | length 563.5
  Top Layer w10: v1(1252.49,3561.1) 1253.06,3561.67 U1.4@1253.06,3623.52 ; v1(1255.44,4699.68) 1258.01,4702.24 U4.4@1258.01,4766.09 ; U6.4@1268.49,2521.48 1268.49,2461.35 C24.1 ; v1(1568.49,4457.23) 1569.48,4457.23 1583.18,4470.93 1583.18,4514.18 1587.63,4518.64 1587.63,4526.52 U5.2 ; U2.2 1586.43,3329.32 v1(1590.41,3325.34) ; v1(1600.37,2236.62) 1600.66,2236.91 U7.2 ; U3.6 1642.69,1723.36 1642.77,1723.28 1655.19,1723.28 1681.47,1697 1695.64,1697 R8.2 v1(1773.65,1684.29) C5.2
  other v1: 1269.56,2460.27
GND: C1.1 C2.2 C4.2 C5.1 C6.1 C7.2 C8.1 C9.1 C14.1 C15.2 C18.1 C19.1 C24.2 C25.1 C28.1 C29.1 C33.2 C34.2 C35.2 C36.1 C37.2 C38.1 C39.2 C40.1 J3.1@1079.34,1848.96 J3.2@1079.34,1691.48 J3.A1 J3.A12 J3.B1 J3.B12 J6.2 J6.4 J6.6 J6.8 J6.10 R1.1 R4.1 R5.2 R6.2 R7.2 R9.1 R10.2 R11.1 R12.2 R13.1 R14.2 R33.2 R35.2 R39.1 R40.2 R42.1 U1.5 U3.4 U3.13 U4.5 U6.5 | length 141.5
  Top Layer w6: v2(1593.47,1765.53) 1603.32,1755.69 U3.4
  Top Layer w10: J3.B1 1108.87,1659.98 1110.83,1661.95 J3.A12 ; J3.B12 1108.87,1880.46 1110.83,1878.49 J3.A1
  other v1: 1630,1609.03 1482.39,1676.3 1316.02,1707.23 1483.44,1729.11 1773.85,1747.08 1317.83,1789.62 1771.34,1813.76 1440.35,1859.62 1663.36,2236.62 1705.69,2302.18 1175.96,2359.17 1425.49,2414.74 1105.43,2417.16 1333.63,2459.2 1481.08,2521.48 1104.21,2551.54 1705.69,2631.26 1625.37,2633.93 1103.62,2748.33 1653.4,3325.34 1687.86,3461.65 1179.18,3466.51 1421.01,3513.01 1102.39,3531.15 1315.49,3561.1 1465.66,3623.52 1102.39,3664.89 1606.16,3733.32 1687.86,3736.55 1102.39,3863.07 1631.48,4457.23 1695.93,4578.7 1176.51,4605.84 1413.61,4652.99 1101.76,4671.18 1318.43,4699.68 1470.61,4766.09 1101.76,4802.88 1698.91,4850.47 1616.32,4866.09 1101.76,4999.1
  other v2: 1551.15,1765.53 1635.8,1765.53
INPUT_1_N: R44.2 U1.2 | length 76.2
  Top Layer w10: R44.2 1187.22,3723.52 U1.2
INPUT_1_P: R45.2 U1.3 | length 77
  Top Layer w10: R45.2 1189.18,3673.52 U1.3
INPUT_2_N: R46.2 U4.2 | length 83.7
  Top Layer w10: R46.2 R46.2@1178.21,4869.09 ; R46.2@1178.21,4866.09 U4.2
INPUT_2_P: R47.2 U4.3 | length 87.6
  Top Layer w10: R47.2 1187.48,4816.09 U4.3
INPUT_3_N: R48.2 U6.2 | length 94
  Top Layer w10: R48.2@1175.96,2627.42 1181.91,2621.48 U6.2
INPUT_3_P: R49.2 U6.3 | length 98.6
  Top Layer w10: R49.2@1175.96,2555.94 1175.96,2556.92 1190.52,2571.48 U6.3
NetC2_1: C2.1 U3.5 | length 49.2
  Top Layer w10: U3.5 1623,1688.86 C2.1
NetC3_1: C3.1 U3.9 | length 100.1
  Top Layer w6: U3.9 1603.42,1803.03 1603.42,1871.81 1608.37,1876.76 C3.1
NetC3_2: C3.2 U3.10 | length 80.5
  Top Layer w6: C3.2 1567.59,1842.33 1583.63,1826.28 U3.10
NetC10_1: C10.1 C11.1 C12.1 R34.2 R36.2 U2.4 | length 506.2
  Top Layer w10: R36.2@1246.26,3438.98 1251.19,3438.98 1261.8,3449.59 C10.1 C11.1 C12.1 1608.42,3449.59 1623.83,3465 1623.83,3510.67 1630.64,3517.48 1674.88,3517.48 R34.2
NetC13_2: C13.2 C21.1 U1.6 | length 154.8
  Top Layer w10: U1.6@1465.66,3673.52 1527,3673.52 C21.1 1537.53,3661.17 1537.53,3586.44 C13.2
NetC16_2: C16.2 C17.1 U4.6 | length 166
  Top Layer w10: U4.6@1470.61,4816.09 1522.21,4816.09 1546.64,4791.65 C17.1 1545.73,4785.75 1545.73,4713.42 C16.2
NetC20_1: C20.1 C22.1 C23.1 R37.2 R38.2 U5.4 | length 516.4
  Top Layer w10: R38.2@1232.74,4580.42 1292.26,4580.42 1297.48,4585.63 1297.56,4585.72 1384.2,4585.72 1470.52,4585.72 C23.1 1614.31,4585.81 1629.13,4600.62 U5.4 1629.13,4642.67 1635.94,4649.48 R37.2
NetC26_1: C26.1 C27.2 U6.6 | length 154.1
  Top Layer w10: U6.6@1481.08,2571.48 1485.55,2567.01 1537.85,2567.01 1552.85,2552.01 1552.85,2549.44 1552.99,2549.3 1552.99,2478.04 C26.1@1553.13,2477.9
NetC30_1: C30.1 C31.1 C32.1 R41.2 R43.2 U7.4 | length 552.1
  Top Layer w10: R43.2@1244.06,2340.52 1248.98,2340.52 1257.04,2348.58 1315.91,2348.58 C32.1 C31.1 1622.42,2348.58 1638.06,2364.22 U7.4 1638.06,2438.25 1643.92,2444.11 1695.65,2444.11 R41.2
NetC33_1: C33.1 J3.A4 J3.A9 J3.B4 J3.B9 R3.1 | length 575.4
  Top Layer w10: J3.B4 1080.4,1721.91 1127.64,1721.91 J3.A9 ; J3.B9 1080.4,1818.53 1127.64,1818.53 J3.A4 1129.46,1820.34 1171.57,1820.34 1226.69,1875.46 R3.1@1255.72,1875.46 ; C33.1 1224.95,1969.73 1256.7,1937.98 R3.1@1256.7,1875.46
  Bottom Layer w10: J3.B4 1080.22,1723.86 1097.77,1723.86 1105.01,1731.1 1105.01,1809.34 1097.77,1816.58 1080.22,1816.58 J3.B9
NetC35_1: C35.1 J1.1 R9.2 R44.1 | length 377.9
  Top Layer w10: J1.1 1176.41,3797.31 R44.1 ; C35.1 R9.2
NetC36_2: C36.2 J1.2 R10.1 R45.1 | length 376.9
  Top Layer w10: J1.2 1175.96,3597.31 R45.1 C36.2
NetC37_1: C37.1 J2.1 R11.2 R46.1 | length 370.6
  Top Layer w10: J2.1 R46.1@1173.29,4934 ; R11.2 C37.1 ; R46.1@1173.29,4937 R46.1
NetC38_2: C38.2 J2.2 R12.1 R47.1 | length 374.6
  Top Layer w10: J2.2 1168.39,4734 R47.1 1174.73,4670.62 R12.1
NetC39_1: C39.1 J3.1@875,2686 R13.2 R48.1 | length 373.8
  Top Layer w10: J3.1@875,2686 1103.62,2686 1171.55,2686 R48.1@1175.96,2690.42 ; R13.2 1103.62,2615.13 C39.1
NetC40_2: C40.2 J3.2@875,2486 R14.1 R49.1 | length 378.3
  Top Layer w10: J3.2@875,2486 1166.5,2486 R49.1 C40.2 C40.2
NetD1_2: D1.2 J6.5 | length 2034.8
  Top Layer w10: J6.5 1771.03,4187.46 1771.03,2258.16 D1.2
NetJ3_A5: J3.A5 R5.1 | length 130.5
  Top Layer w10: J3.A5 1244.7,1799.75 R5.1
NetJ3_B5: J3.B5 R6.1 | length 383.4
  Bottom Layer w10: J3.B5 1047.56,1738.72 1041.73,1732.9 1041.15,1732.9 1026.11,1717.86 1026.11,1665.1 1056.89,1634.32 1225.21,1634.32 1253.02,1662.13 v1(1253.02,1707.23)
NetR1_2: R1.2 U2.3 | length 64.2
  Top Layer w10: U2.3 1687.37,3399.16 R1.2
NetR2_2: R2.2 R4.2 U3.2 | length 125.2
  Top Layer w6: R2.2 R4.2 1553.66,1684.57 1553.66,1700.48 1563.95,1710.77 U3.2
NetR7_1: R7.1 R8.1 U3.7 | length 136.6
  Top Layer w10: U3.7 1697.53,1802.93 R7.1 R8.1
NetR15_1: R15.1 R16.2 SW1.11 | length 221.9
  Top Layer w10: SW1.11 1466.2,3985.06 1526.07,3925.19 R16.2 1524.85,3922.98 R15.1
NetR15_2: R15.2 SW1.12 | length 200.8
  Top Layer w10: SW1.12 1571.31,4043.68 1571.31,3861.83 R15.2
NetR16_1: R16.1 R17.2 SW1.10 | length 241
  Top Layer w10: SW1.10 1372.72,4045.42 1372.72,4016.53 1449.38,3939.87 1449.38,3938.89 1463.08,3925.19 R16.1 1455.44,3916.57 R17.2
NetR17_1: R17.1 R18.2 SW1.9 | length 248.6
  Top Layer w10: SW1.9 1269.35,4043.44 1387.6,3925.19 R18.2 1388.58,3857.23 R17.1
NetR18_1: R18.1 R19.2 SW1.8 | length 282.4
  Top Layer w10: SW1.8 1175.58,4045.72 1205.06,4045.72 1310.9,3939.87 1310.9,3938.89 1324.6,3925.19 R18.1 1317.59,3917.19 R19.2
NetR19_1: R19.1 R20.1 SW1.7 | length 300.4
  Top Layer w10: SW1.7 1147.6,3975.27 1194.14,3975.27 1244.1,3925.31 R20.1 1245.09,3862.71 R19.1
NetR21_1: R21.1 R22.2 SW2.11 | length 196.9
  Top Layer w10: R21.1 1555.55,5051.75 R22.2 1561.33,5062.73 SW2.11
NetR21_2: R21.2 SW2.12 | length 231.7
  Top Layer w10: R21.2 1639.72,4989.98 1659.75,5010.01 SW2.12
NetR22_1: R22.1 R23.2 SW2.10 | length 210
  Top Layer w10: SW2.10 1500.93,5144.3 R22.1 1496.26,5055.46 R23.2
NetR23_1: R23.1 R24.2 SW2.9 | length 220.8
  Top Layer w10: SW2.9 1426.07,5120.74 R24.2 1426.07,4997.18 R23.1
NetR24_1: R24.1 R25.2 SW2.8 | length 234.3
  Top Layer w10: SW2.8 1360.41,5087.97 1360.41,5062.8 R24.1 1356.51,5053.56 R25.2
NetR25_1: R25.1 R26.1 SW2.7 | length 244.1
  Top Layer w10: SW2.7 1167.63,5177.36 1283.28,5061.71 R26.1 1284.26,5000.16 R25.1
NetR27_1: R27.1 R28.2 SW3.11 | length 187.8
  Top Layer w10: R27.1 1532.97,2808.47 R28.2 1546.33,2821.83 SW3.11
NetR27_2: R27.2 SW3.12 | length 229.4
  Top Layer w10: R27.2 1586.22,2744.14 1625.33,2744.14 1644.76,2763.56 SW3.12
NetR28_1: R28.1 R29.2 SW3.10 | length 193.6
  Top Layer w10: SW3.10 1474.05,2900.13 R28.1@1474.05,2813.53 ; R29.2 1475.04,2745.38 R28.1
NetR29_1: R29.1 R30.2 SW3.9 | length 207.6
  Top Layer w10: SW3.9 1400.92,2874.84 R30.2 1400.92,2753.8 R29.1
NetR30_1: R30.1 R31.2 SW3.8 | length 227
  Top Layer w10: SW3.8 1262.73,2926.27 1275.28,2913.72 1277.3,2913.72 1335.96,2855.06 1335.96,2815.49 R30.1 1337.93,2745.81 R31.2
NetR31_1: R31.1 R32.1 SW3.7 | length 246
  Top Layer w10: SW3.7 1160.89,2918.02 1182.03,2918.02 1259.07,2840.98 1259.07,2819.68 R32.1 1265.61,2755.13 R31.1
NetR39_2: R39.2 U5.3 | length 73.5
  Top Layer w10: U5.3 1682.02,4530.61 1695.93,4516.7 R39.2
NetR42_2: R42.2 U7.3 | length 116.1
  Top Layer w10: U7.3 1638.06,2328.89 1665.38,2356.21 1696.74,2356.21 R42.2
"Phase A": C10.2 C11.2 C12.2 J6.7 R36.1 U2.1 | length 1533
  Top Layer w10: R36.1 1303.81,3387.59 C10.2 C11.2 v1(1472.12,3376.76) 1484.67,3389.31 1542.21,3389.31 1549.03,3396.13 U2.1
  Bottom Layer w10: v1(1472.12,3376.76) 1393.38,3376.76 1372.72,3397.42 1372.72,3681.64 1636.77,3945.7 1636.77,4287.94 1679.69,4330.85 J6.7
"Phase B": C20.2 C22.2 C23.2 J6.9 R38.1 U5.1 | length 757.4
  Top Layer w10: R38.1@1232.74,4523.33 1286.94,4523.33 1297.48,4512.8 1297.56,4512.88 C20.2@1384.2,4512.88 ; C20.2@1393.06,4512.8 1384.2,4512.8 1384.2,4443.38 1401.93,4425.65 1722.45,4425.65 J6.9 ; C20.2@1393.06,4512.88 1470.52,4512.88 C23.2 1478.4,4520.76 1547.51,4520.76 1554.32,4527.57 U5.1
"Phase C": C30.2 C31.2 C32.2 J6.1 R43.1 U7.1 | length 2446
  Top Layer w10: R43.1@1244.06,2283.44 1475.03,2283.44 v1(1482.72,2275.75) 1489.26,2282.29 1556.45,2282.29 1563.26,2289.1 U7.1
  Bottom Layer w10: v1(1482.72,2275.75) 1498.02,2291.04 1600.14,2291.04 1613.87,2277.31 1787.73,2277.31 1807.32,2296.9 1807.32,3951.18 J6.1
SW_Phase_A: C13.1 C21.2 R33.1 R34.1 | length 231.9
  Top Layer w10: C21.2 1617.53,3661.17 1617.53,3586.44 C13.1 1679.94,3585.54 R34.1 R33.1
SW_Phase_B: C16.1 C17.2 R35.1 R37.1 | length 222.2
  Top Layer w10: C17.2 1625.73,4785.75 1625.73,4713.42 C16.1 R37.1 R37.1 1698.91,4715.46 R35.1
SW_Phase_C: C26.2 C27.1 R40.1 R41.1 | length 214.6
  Top Layer w10: C26.2 1635.55,2493.39 1635.55,2564.65 C27.1 1702.22,2564.79 R40.1 R41.1
VCC: C1.2 C34.1 D1.1 R3.2 U3.3 U3.8 U3.12
pads on no net: J3.3 J3.4 J3.5 J3.6 J3.7 J3.8 J3.A2 J3.A3 J3.A6 J3.A7 J3.A8 J3.A10 J3.A11 J3.B2 J3.B3 J3.B6 J3.B7 J3.B8 J3.B10 J3.B11 J6.3 U3.1

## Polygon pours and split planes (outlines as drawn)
+2V5 on Layer 3 "LAYER_3_+2V5_P008" (solid, remove dead copper, pour order 8): 774.75,1559.49 717.49,1616.75 717.49,5645.03 789.53,5717.07 2085.11,5717.07 2154.45,5647.73 2154.45,1622.64 2091.29,1559.49
GND on Layer 2 "LAYER_2_GND_P007" (solid, remove dead copper, pour order 7): 774.75,1559.49 717.49,1616.75 717.49,5644.13 790.43,5717.07 2085.11,5717.07 2154.45,5647.73 2154.45,1622.64 2091.29,1559.49
-2V5 on Bottom Layer "BOTTOM_LAYER_-2V5_P003" (solid, remove dead copper, pour order 3): 774.75,1559.49 717.49,1616.75 717.49,5644.13 790.42,5717.07 2085.11,5717.07 2154.45,5647.73 2154.45,1622.64 2091.29,1559.49
VCC on Top Layer "TOP_LAYER_VCC_P000" (solid, remove dead copper, pour order 0): 2083.15,5717.07 2154.45,5645.77 2154.45,1622.64 2075.64,1543.84 790.4,1543.84 717.49,1616.75 717.49,5643.35 789.53,5717.07

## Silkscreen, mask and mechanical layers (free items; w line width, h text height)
Top Overlay:
  text "TIDA-010986" at 1149.23,5638.49 h60
  text "G= 1, 50, 100, 140, 210, 420, 525" at 941.04,5565.85 h26
  text "Phase B" at 846.64,5460.55 h35 r270
  text "Phase A" at 817.11,4323.85 h35 r270
  text "Phase C" at 830.45,3212.88 h35 r270
M1 Board Outline:
  the board outline again, w10
M9 Title Sheet:
  drawing of 57 lines, arcs and shapes, not listed
  text "1" at 1431.84,9570.5 h70
  text "2" at 3927.5,9570.5 h70
  text "3" at 6416.84,9570.5 h70
  text "4" at 8923.51,9570.5 h70
  text "5" at 11422.5,9570.5 h70
  text "6" at 13927.5,9570.5 h70
  text "A" at 275.5,8427.5 h70
  text "A" at 15075.5,8427.5 h70
  text "B" at 275.5,6047.5 h70
  text "B" at 15075.5,6047.5 h70
  text "C" at 275.5,3672.5 h70
  text "C" at 15075.5,3672.5 h70
  text "PROJECT TITLE:" at 12035.5,1811.5 h45
  text ".PRJ_Title" at 12085.5,1678.17 h70
  text "DESIGNED FOR:" at 12035.5,1510.5 h45
  text ".PRJ_Customer" at 12085.5,1370.5 h70
  text "D" at 275.5,1302.5 h70
  text "D" at 15075.5,1302.5 h70
  text "FILE NAME:" at 12035.5,1210.5 h45
  text ".PCB_File_Name_No_Path" at 12085.5,1090.5 h70
  text "Texas Instruments (TI) and/or its licensors do not warrant the accuracy or completeness of this specification" at 7066,928.66 h45
  text "ENGINEER:" at 12035.5,920.5 h45
  text "LAYOUT BY:" at 13540.5,920.5 h45
  text "or any information contained therein. TI and/or its licensors do not warrant that this design will meet" at 7021.01,816 h45
  text ".PRJ_Engineer" at 12085.5,765.51 h70
  text ".PCB_Layout" at 13591,765.51 h70
  text "the specifications, will be suitable for your application or fit for any particular purpose, or will operate in" at 7021.01,703.33 h45
  text ".Layer_Name" at 1269,675.51 h60
  text "ALTIUM DESIGNER VERSION:" at 13540.5,610.5 h45
  text "an implementation. TI and/or its licensors do not warrant that the design is production worthy. You should" at 7021.01,590.67 h45
  text "completely validate and test your design implementation to confirm the system functionality for your application." at 7066,478 h45
  text ".print_Scale" at 12085.5,477.17 h70
  text ".Application_BuildNumber" at 13591,477.17 h70
  text "1" at 1431.84,270.5 h70
  text "2" at 3927.5,270.5 h70
  text "3" at 6416.84,270.5 h70
  text "4" at 8923.51,270.5 h70
  text "5" at 11422.5,270.5 h70
  text "6" at 13927.5,270.5 h70

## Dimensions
692,1534 to 692,1534 on M2 Board Dimensions
692,1534 to 2188.06,5736.76 on M2 Board Dimensions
